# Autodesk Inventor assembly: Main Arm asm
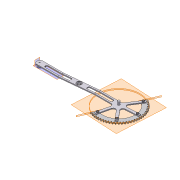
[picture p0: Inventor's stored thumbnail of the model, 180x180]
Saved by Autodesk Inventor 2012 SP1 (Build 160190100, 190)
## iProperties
Created: 2006-09
Part Number: Main Arm asm
Document SubType Name: Assembly
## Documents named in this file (8)
- D:\Backup\CMU Work Temp\XX\Inv2012DynSim\Sub-Assemblies\Main Arm asm.iam
- D:\Backup\CMU Work Temp\XX\Inv2012DynSim\Parts\Main Arm.ipt
- D:\Backup\CMU Work Temp\XX\Inv2012DynSim\Parts\Spur Gear22.ipt
- D:\Backup\CMU Work Temp\XX\Inv2012DynSim\Parts\Pin.ipt
- D:\Backup\CMU Work Temp\XX\Inv2012DynSim\Sub-Assemblies\Bolted Connection1.iam
- D:\Backup\CMU Work Temp\XX\Inv2012DynSim\Sub-Assemblies\Bolted Connection5.iam
- D:\Backup\CMU Work Temp\XX\Inv2012DynSim\Sub-Assemblies\Bolted Connection6.iam
- D:\Backup\CMU Work Temp\XX\Inv2012DynSim\Sub-Assemblies\Bolted Connection7.iam
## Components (7 placed, 4 different names)
1. Main Arm:1 — Mate:5, Flush:1, Mate:6, Mate:7, Mate:8, Mate:9, Mate:10, Mate:11, Mate:12, Mate:13, Mate:14
2. Spur Gear2:1 — Mate:5, Mate:6
3. Pin:1 — Flush:1
4. Bolted Connection:1 [sub-assembly] — Mate:7, Mate:8
5. Bolted Connection:2 [sub-assembly] — Mate:9, Mate:10
6. Bolted Connection:3 [sub-assembly] — Mate:11, Mate:12
7. Bolted Connection:4 [sub-assembly] — Mate:13, Mate:14
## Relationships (11: Mate 10, Flush 1)
- Mate:5: Main Arm:1 ↔ Spur Gear2:1
- Flush:1: Main Arm:1 ↔ Pin:1
- Mate:6: Main Arm:1 ↔ Spur Gear2:1
- Mate:7: Main Arm:1 ↔ Bolted Connection:1
- Mate:8: Main Arm:1 ↔ Bolted Connection:1
- Mate:9: Main Arm:1 ↔ Bolted Connection:2
- Mate:10: Main Arm:1 ↔ Bolted Connection:2
- Mate:11: Main Arm:1 ↔ Bolted Connection:3
- Mate:12: Main Arm:1 ↔ Bolted Connection:3
- Mate:13: Main Arm:1 ↔ Bolted Connection:4
- Mate:14: Main Arm:1 ↔ Bolted Connection:4
